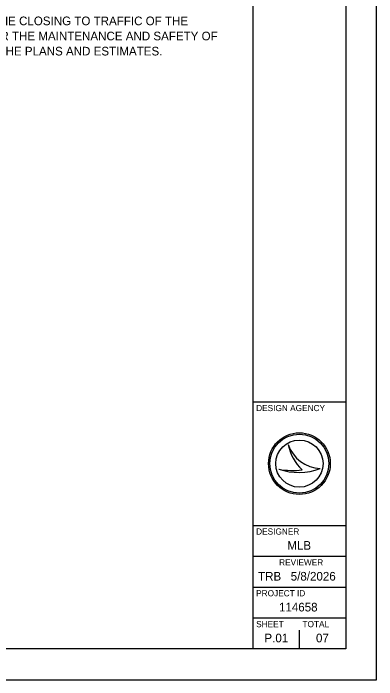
# Model space of a CAD drawing. Extents: x 0 to 34, y 0 to 22.
# Drawn here: x 28.12 to 34, y 0 to 10.79 of the extents above; entities that cross this region are included whole.
import ezdxf

# ---------------------------------------------------------------- set-up
doc = ezdxf.new("R2010")
doc.units = 0
for name, color, linetype in [('SH_Border', 7, 'Continuous'), ('SH_Cut_Line', 7, 'Continuous'), ('SH_Data', 7, 'Continuous'), ('SH_Text', 7, 'Continuous')]:
    doc.layers.add(name, color=color, linetype=linetype)

msp = doc.modelspace()

# ---------------------------------------------------------------- linework, layer by layer
at = {"layer": 'SH_Border'}
for p, q in [((32, 0.5), (32, 21.5)), ((32, 4.5), (33.5, 4.5)), ((32, 2.5), (33.5, 2.5)), ((32, 2), (33.5, 2)), ((32, 1.5), (33.5, 1.5)), ((32, 1), (33.5, 1))]:
    msp.add_line(p, q, dxfattribs=at)
msp.add_lwpolyline([(1.5, 21.5), (33.5, 21.5), (33.5, 0.5), (1.5, 0.5)], close=True, dxfattribs=at)
at = {"layer": 'SH_Cut_Line'}
msp.add_lwpolyline([(0, 0), (34, 0), (34, 22), (0, 22)], close=True, dxfattribs=at)
at = {"layer": 'SH_Data'}
for p, q in [((32.567, 3.81), (32.567, 3.81)), ((32.75, 3.5), (32.75, 3.5)), ((32.417, 3.41), (32.417, 3.41)), ((33.087, 3.419), (33.087, 3.419)), ((32.75, 0.5), (32.75, 0.8)), ((32.375, 0.675), (32.375, 0.675))]:
    msp.add_line(p, q, dxfattribs=at)
for radius in [0.5, 0.477, 0.477, 0.382]:
    msp.add_circle((32.75, 3.5), radius, dxfattribs=at)
for centre, radius, start, end in [((33.116, 3.998), 0.58, 198.9257, 198.9319), ((33.347, 3.97), 0.796, 191.6379, 191.6421), ((33.116, 3.998), 0.58, 198.9319, 267.1657), ((33.347, 3.97), 0.796, 191.6421, 226.0947), ((32.739, 4.37), 1.013, 251.4576, 290.0832), ((32.648, 4.654), 1.266, 259.4964, 259.4995), ((32.739, 4.37), 1.013, 251.4527, 251.4576), ((32.648, 4.654), 1.266, 259.4995, 276.6672)]:
    msp.add_arc(centre, radius, start, end, dxfattribs=at)

# ---------------------------------------------------------------- texts
for s, height, p in [('DESIGN AGENCY', 0.1, (32.05, 4.35)), ('DESIGNER', 0.1, (32.05, 2.35)), ('MLB', 0.14, (32.554, 2.105)), ('REVIEWER', 0.1, (32.422, 1.85)), ('TRB', 0.14, (32.081, 1.605)), ('5/8/2026', 0.14, (32.609, 1.605)), ('PROJECT ID', 0.1, (32.05, 1.35)), ('114658', 0.14, (32.419, 1.105)), ('SHEET', 0.1, (32.05, 0.85)), ('TOTAL', 0.1, (32.8, 0.85)), ('P.01', 0.14, (32.184, 0.605)), ('07', 0.14, (33.018, 0.605))]:
    msp.add_text(s, height=height, dxfattribs=at).set_placement(p)
at = {"layer": 'SH_Text'}
for s, p in [('IMPROVEMENT WILL NOT REQUIRE THE CLOSING TO TRAFFIC OF THE ', (24.5, 10.601)), ('HIGHWAY AND THAT PROVISIONS FOR THE MAINTENANCE AND SAFETY OF ', (24.5, 10.356)), ('TRAFFIC WILL BE AS SET FORTH ON THE PLANS AND ESTIMATES.', (24.5, 10.111))]:
    msp.add_text(s, height=0.14, dxfattribs=at).set_placement(p)

doc.saveas('drawing.dxf')
